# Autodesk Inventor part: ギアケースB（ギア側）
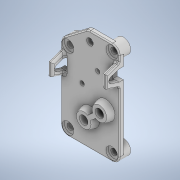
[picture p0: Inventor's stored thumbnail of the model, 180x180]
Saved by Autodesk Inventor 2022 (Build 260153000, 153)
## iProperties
Created: 2024-09
Part Number: ギアケースB（ギア側）
Material: 一般
Document SubType Name: Modeling
Designer: shimizu
Density: 1 g/cm^3
Appearance: 既定
Author: shimizu
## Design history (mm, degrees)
sketch "スケッチ1"
  geometry: L1 (0, 35.5)-(10.5, 35.5); L2 (14, 32)-(14, -10); L3 (10.5, -13.5)-(-10.5, -13.5); L4 (-14, -10)-(-14, 24); L5 (-2.121, 34.784)-(-12.621, 26.784); A1 r 3.5 centre (0, 32) between (0, 35.5) and (-2.121, 34.784); A2 r 3.5 centre (-10.5, 24) between (-12.621, 26.784) and (-14, 24); A3 r 3.5 centre (10.5, 32) between (14, 32) and (10.5, 35.5); A4 r 3.5 centre (10.5, -10) between (10.5, -13.5) and (14, -10); A5 r 3.5 centre (-10.5, -10) between (-14, -10) and (-10.5, -13.5); 1 further point
  constraints: 10 end point, 10 point on circle, 10 tangent, 5 centre point, 2 equal radius, 2 parallel, 1 horizontal, 1 perpendicular, 1 vertical alignment
  dimensions: "d0" = 13.5 distance from line of L3 point (0, 0); "d1" = 49 distance between parallel lines of L1 L3; "d2" = 28 distance between parallel lines of L2 L4; "d3" = 14 distance from line of L2 point (0, 0); "d4" = 7 diameter of A1; "d5" = 7 diameter of A2; "d6" = 24 vertical distance of point (0, 0) A2.centre; "d7" = 3.5 radius of A3
extrude "押し出し1" new body sketch "スケッチ1" distance "d8" = 2; taper "d9" = 0 deg
sketch "スケッチ2"
  geometry: C1 r 3.5 at (-10.5, 32); C2 r 3.5 at (10.5, 24); C3 r 3.5 at (-10.5, -10); C4 r 3.5 at (10.5, -10); A1 r 3.5 centre (-10.5, -10) between (-14, -10) and (-10.5, -13.5) reference; A2 r 3.5 centre (10.5, -10) between (10.5, -13.5) and (14, -10) reference; A3 r 3.5 centre (10.5, 24) between (14, 24) and (12.621, 26.784) reference; A4 r 3.5 centre (-10.5, 32) between (-10.5, 35.5) and (-14, 32) reference; 1 further point
  constraints: 8 concentric, 4 centre point
extrude "押し出し2" join sketch "スケッチ2" distance "d10" = 3.5; taper "d11" = 0 deg
sketch "スケッチ3"
  geometry: C1 r 3 at (0, 0); C2 r 3 at (21, -8); C3 r 3 at (0, -42); C4 r 3 at (21, -42); C5 r 3.5 at (0, 0) reference; C6 r 3.5 at (21, -8) reference; C7 r 3.5 at (0, -42) reference; C8 r 3.5 at (21, -42) reference; 1 further point
  constraints: 4 centre point, 4 concentric, 3 equal radius
  dimensions: "d12" = 6 diameter of C1
extrude "押し出し3" cut sketch "スケッチ3" distance "d13" = 0.5; taper "d14" = 0 deg
sketch "スケッチ4"
  geometry: C1 r 4.5 at (7.5, 6.5); C2 r 4.5 at (0, 0); 1 further point
  constraints: 2 centre point, 1 coincident
  dimensions: "d15" = 9 diameter of C2; "d16" = 9 diameter of C1; "d17" = 6.5 vertical distance of point (0, 0) C1.centre; "d18" = 7.5 horizontal distance of point (0, 0) C1.centre
extrude "押し出し4" join sketch "スケッチ4" distance "d19" = 3; taper "d20" = -18.4 deg
sketch "スケッチ5"
  geometry: L1 (7.5, 6.5)-(0, 0); L2 (6.845, 7.256)-(-0.655, 0.756); L3 (8.155, 5.744)-(0.655, -0.756); L4 (6.845, 7.256)-(8.155, 5.744); L5 (-0.655, 0.756)-(0.655, -0.756); C1 r 2.336 at (7.5, 6.5); C2 r 2.527 at (0, 0); C3 r 3.502 at (7.5, 6.5) reference; C4 r 3.502 at (0, 0) reference; 5 further points
  constraints: 10 end point, 5 parallel, 2 centre point, 2 coincident, 2 concentric, 1 midpoint, 1 perpendicular
  dimensions: "d21" = 1 distance between parallel lines of L1 L2; "d22" = 1 distance between parallel lines of L1 L3
extrude "押し出し5" join sketch "スケッチ5" stored distance "d23" = 3; taper "d24" = 0 deg
sketch "スケッチ6"
  geometry: C1 r 3 at (3.76, 11.92); 1 further point
  constraints: 1 centre point
  dimensions: "d25" = 6 diameter of C1; "d26" = 3.76 horizontal distance of point (0, 0) C1.centre; "d27" = 11.92 vertical distance of point (0, 0) C1.centre
extrude "押し出し6" join sketch "スケッチ6" distance "d28" = 4; taper "d29" = -7.1 deg
sketch "スケッチ7"
  geometry: L1 (-3.72, 20.65)-(6.28, 20.65); L2 (-3.72, 20.65)-(6.28, 20.65); L3 (-3.72, 20.65)-(-3.72, 10.65); L4 (-3.72, 20.65)-(6.28, 20.65); L5 (-3.72, 20.65)-(-3.72, 10.65); A1 r 10 centre (-3.72, 20.65) between (-3.72, 10.65) and (6.28, 20.65); 2 further points
  constraints: 10 end point, 3 collinear, 2 point on circle, 1 centre point, 1 horizontal
  dimensions: "d30" = 0 distance between parallel lines of L1 L2; "d31" = 90 deg angle of L3 L1; "d33" = 3.72 horizontal distance of point (0, 0) L1.start; "d34" = 20.65 vertical distance of point (0, 0) L1.start; "d35" = 10 radius of A1
extrude "押し出し7" cut sketch "スケッチ7" extent not by distance; stored distance "d36" = 0; taper "d37" = 0 deg
sketch "スケッチ8"
  geometry: C1 r 1.05 at (3.72, 20.65); C2 r 1.05 at (-3.76, 11.92); C3 r 1.6 at (0, 31); C4 r 1.5 at (-10.5, 24); C5 r 1.5 at (10.5, 32); C6 r 1.5 at (-10.5, -10); C7 r 1.5 at (10.5, -10); C8 r 3 at (-10.5, 24) reference; C9 r 3 at (10.5, 32) reference; C10 r 3 at (-10.5, -10) reference; C11 r 3 at (10.5, -10) reference; C12 r 2.05 at (7.5, 6.5); C13 r 2.05 at (0, 0); A1 r 10 centre (3.72, 20.65) between (-4.423, 14.846) and (-0.767, 11.713) reference; A2 r 2.502 centre (-3.76, 11.92) between (-4.087, 14.4) and (-1.259, 11.978) reference; A3 r 3.502 centre (7.5, 6.5) between (5.619, 3.546) and (4.309, 5.058) reference; A4 r 3.502 centre (0, 0) between (1.881, 2.954) and (3.191, 1.442) reference; 1 further point
  constraints: 9 centre point, 8 concentric, 3 equal radius, 1 vertical alignment
  dimensions: "d38" = 2.1 diameter of C1; "d39" = 2.1 diameter of C2; "d40" = 3.2 diameter of C3; "d41" = 31 distance of point (0, 0) C3.centre; "d42" = 3 diameter of C4; "d43" = 4.1 diameter of C12; "d44" = 4.1 diameter of C13
extrude "押し出し8" cut sketch "スケッチ8" extent not by distance; stored distance "d45" = 3; taper "d46" = 0 deg
sketch "スケッチ9"
  geometry: L1 (-8.764, 34.013)-(16.229, 34.013); L2 (-8, 37.013)-(-8, 31.013); L3 (-8, 37.013)-(-2, 39.013); L4 (-2, 0)-(-2, 42) reference; L5 (-8, 31.013)-(-2, 29.013); L6 (-2, 36.761)-(-5.974, 35.436); L7 (-2, 31.265)-(-5.974, 32.59); A1 r 1.5 centre (-5.5, 34.013) between (-5.974, 35.436) and (-5.974, 32.59); 1 further point
  constraints: 12 end point, 5 point on line, 2 parallel, 2 point on circle, 2 tangent, 1 centre point, 1 horizontal, 1 vertical
  dimensions: "d47" = 6 distance of L2.start L2.end; "d48" = 3 distance from line of L1 L2.start; "d49" = 5 distance from line of L1 L3.end; "d50" = 5 distance from line of L1 L5.end; "d51" = 6 distance between parallel lines of L4 L2; "d52" = 3 diameter of A1; "d53" = 3.5 distance from line of L4 A1.centre
extrude "押し出し9" join sketch "スケッチ9" distance "d54" = 2; taper "d55" = 0 deg
sketch "スケッチ10"
  geometry: L1 (-2, 36.761)-(-5.974, 35.436) reference; L2 (0, 0)-(0, 42) reference; L3 (-2, 36.761)-(0, 36.761); L4 (0, 36.761)-(0, 31.265); L5 (0, 31.265)-(-2, 31.265); L6 (-2, 31.265)-(-2, 36.761); L7 (-2, 31.265)-(-5.974, 32.59) reference; 2 further points
  constraints: 8 end point, 2 parallel, 2 point on line, 1 horizontal, 1 perpendicular
extrude "押し出し10" cut sketch "スケッチ10" distance "d56" = 3; taper "d57" = 0 deg
sketch "スケッチ11"
  geometry: L1 (-19.547, 26)-(25.335, 26); L2 (8, 29)-(8, 23); L3 (2, 34)-(2, 0) reference; L4 (8, 29)-(2, 31); L5 (8, 23)-(2, 21); L6 (2, 28.748)-(5.974, 27.423); L7 (5.974, 24.577)-(2, 23.252); L8 (2, 22.97)-(2, 20.87) reference; A1 r 1.5 centre (5.5, 26) between (5.974, 24.577) and (5.974, 27.423); 2 further points
  constraints: 12 end point, 5 point on line, 2 parallel, 2 point on circle, 2 tangent, 1 centre point, 1 horizontal, 1 vertical
  dimensions: "d58" = 16 distance from line of point (0, 10) L1; "d59" = 6 distance of L2.start L2.end; "d60" = 3 distance from line of L2.start L1; "d61" = 6 distance between parallel lines of L3 L2; "d62" = 5 distance from line of L1 L4.end; "d63" = 5 distance from line of L1 L5.end; "d64" = 3 diameter of A1; "d65" = 3.5 distance from line of L3 A1.centre
extrude "押し出し11" join sketch "スケッチ11" distance "d66" = 2; taper "d67" = 0 deg
sketch "スケッチ12"
  geometry: L1 (0, 34)-(0, 0) reference; L2 (2, 0)-(2, 29.013) reference; L3 (0, 28.748)-(2, 28.748); L4 (2, 28.748)-(2, 23.252); L5 (2, 23.252)-(0, 23.252); L6 (0, 23.252)-(0, 28.748); 2 further points
  constraints: 8 end point, 2 parallel, 1 horizontal, 1 perpendicular, 1 point on line
extrude "押し出し12" cut sketch "スケッチ12" distance "d68" = 3; taper "d69" = 0 deg
fillet "フィレット1" dims "d70" = 1
sketch "スケッチ13"
  geometry: C1 r 2.8 at (10.5, 32); C2 r 2.8 at (-10.5, 24); C3 r 2.8 at (10.5, -10); C4 r 2.8 at (-10.5, -10); C5 r 1.5 at (10.5, 32) reference; C6 r 1.5 at (-10.5, 24) reference; C7 r 1.5 at (10.5, -10) reference; C8 r 1.5 at (-10.5, -10) reference; 1 further point
  constraints: 4 centre point, 4 concentric, 3 equal radius
  dimensions: "d71" = 5.6 diameter of C1
extrude "押し出し13" cut sketch "スケッチ13" distance "d72" = 1; taper "d73" = 0 deg
fillet "フィレット2" dims "d74" = 0.5
node "ソリッド1"
